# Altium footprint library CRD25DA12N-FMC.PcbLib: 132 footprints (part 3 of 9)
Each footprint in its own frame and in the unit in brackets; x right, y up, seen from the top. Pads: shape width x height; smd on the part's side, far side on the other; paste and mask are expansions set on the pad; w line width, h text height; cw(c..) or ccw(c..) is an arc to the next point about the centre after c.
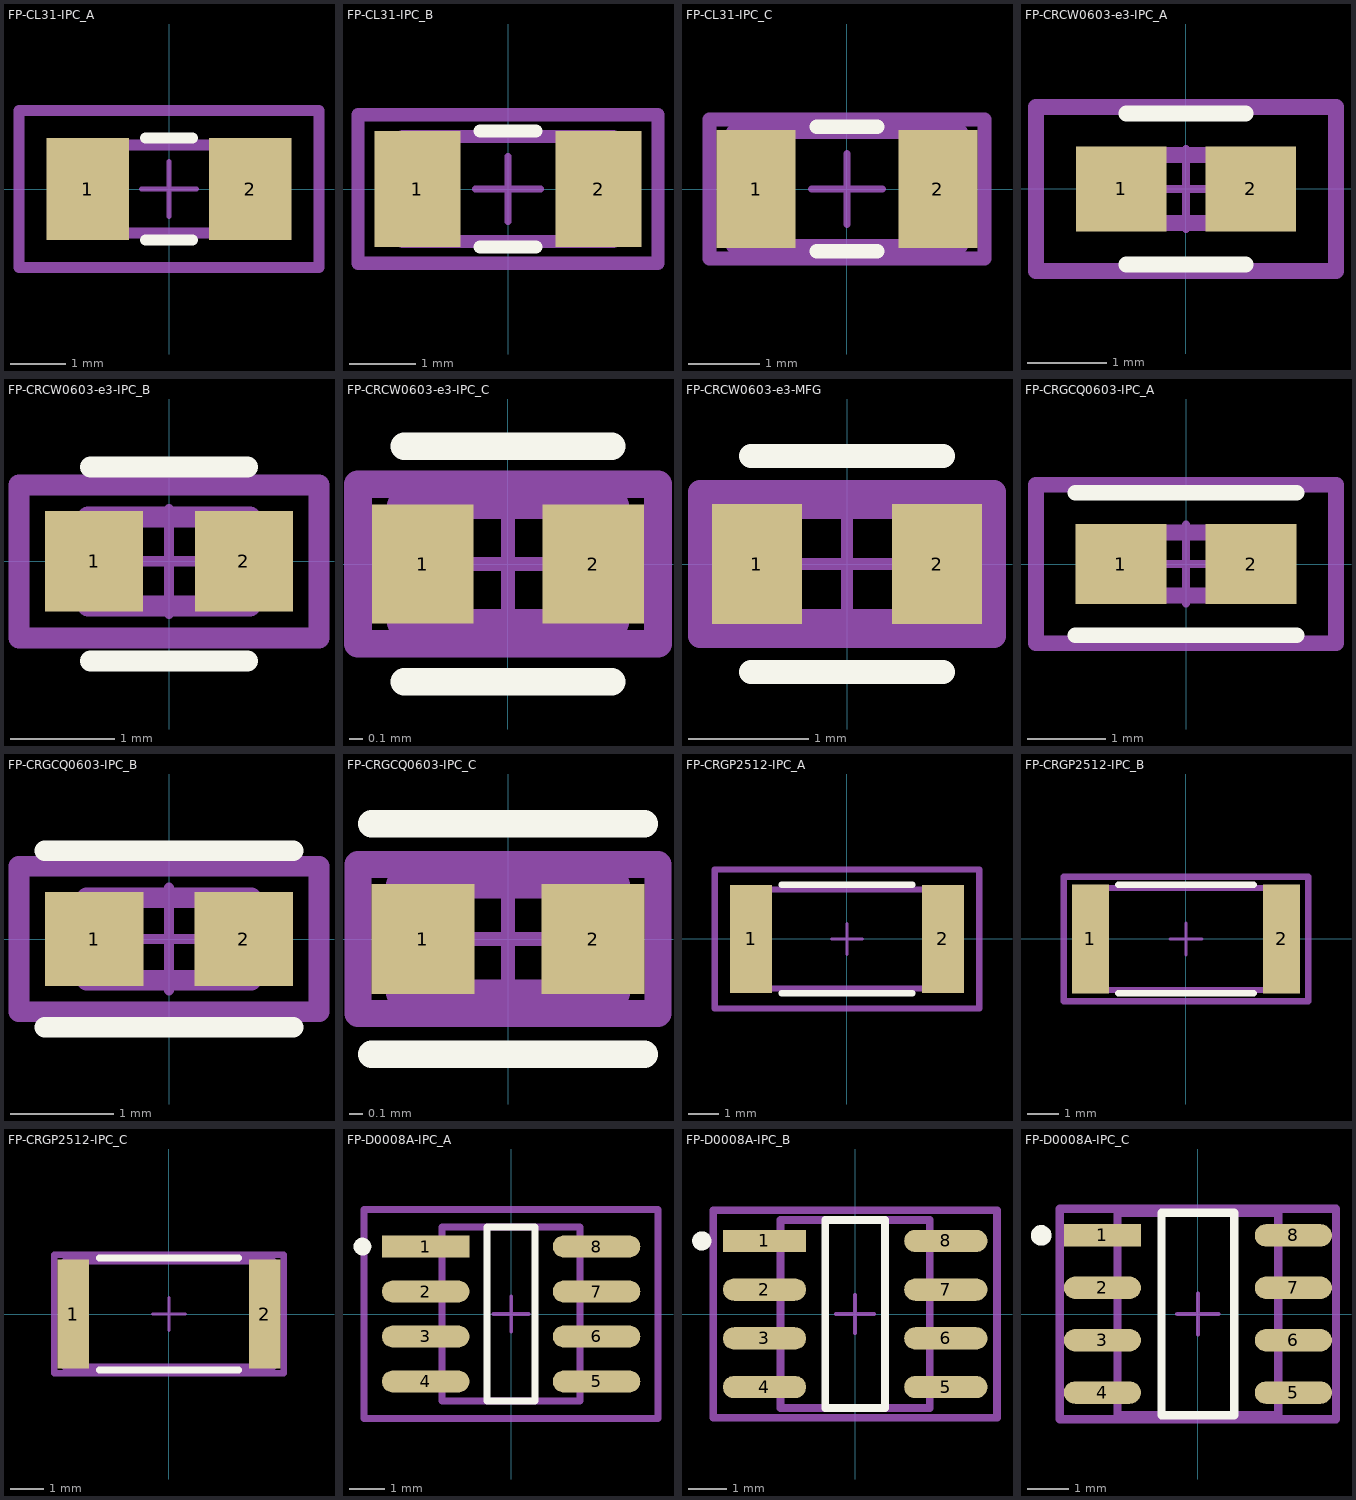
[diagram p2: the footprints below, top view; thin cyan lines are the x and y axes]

## FP-CL31-IPC_A [mm]
pads (2):
  rect 1.505x1.858 smd paste+0 mask+0: 1(-1.476,0) 2(1.476,0)
Top Overlay:
  lines w0.2: -0.424,-0.929 0.424,-0.929 ; -0.424,0.929 0.424,0.929
Mechanical 5:
  lines w0.2: -2.729,-1.429 -2.729,1.429 2.729,1.429 2.729,-1.429 -2.729,-1.429
  text ".Designator" at 0,0.188 h1
Mechanical 13:
  lines w0.2: -1.6,-0.8 -1.6,0.8 1.6,0.8 1.6,-0.8 -1.6,-0.8
Mechanical 15:
  lines w0.2: -2.729,-1.429 -2.729,1.429 2.729,1.429 2.729,-1.429 -2.729,-1.429
Mechanical 16:
  lines w0.1: -0.5,0 0.5,0 ; 0,-0.5 0,0.5
3D body "Cap_Samsung_CL31B105KOFNNNE_eec.STEP": height 0.25, standoff 0, extent -2.729,-1.429 2.729,1.429

## FP-CL31-IPC_B [mm]
pads (2):
  rect 1.305x1.758 smd paste+0 mask+0: 1(-1.376,0) 2(1.376,0)
Top Overlay:
  lines w0.2: -0.424,-0.879 0.424,-0.879 ; -0.424,0.879 0.424,0.879
Mechanical 5:
  lines w0.2: -2.279,-1.129 -2.279,1.129 2.279,1.129 2.279,-1.129 -2.279,-1.129
  text ".Designator" at 0,0.188 h1
Mechanical 13:
  lines w0.2: -1.6,-0.8 -1.6,0.8 1.6,0.8 1.6,-0.8 -1.6,-0.8
Mechanical 15:
  lines w0.2: -2.279,-1.129 -2.279,1.129 2.279,1.129 2.279,-1.129 -2.279,-1.129
Mechanical 16:
  lines w0.1: -0.5,0 0.5,0 ; 0,-0.5 0,0.5
3D body "Cap_Samsung_CL31B105KOFNNNE_eec.STEP": height 0.25, standoff 0, extent -2.279,-1.129 2.279,1.129

## FP-CL31-IPC_C [mm]
pads (2):
  rect 1.105x1.658 smd paste+0 mask+0: 1(-1.276,0) 2(1.276,0)
Top Overlay:
  lines w0.2: -0.424,-0.875 0.424,-0.875 ; -0.424,0.875 0.424,0.875
Mechanical 5:
  lines w0.2: -1.929,-0.975 -1.929,0.975 1.929,0.975 1.929,-0.975 -1.929,-0.975
  text ".Designator" at 0,0.188 h1
Mechanical 13:
  lines w0.2: -1.6,-0.8 -1.6,0.8 1.6,0.8 1.6,-0.8 -1.6,-0.8
Mechanical 15:
  lines w0.2: -1.929,-0.975 -1.929,0.975 1.929,0.975 1.929,-0.975 -1.929,-0.975
Mechanical 16:
  lines w0.1: -0.5,0 0.5,0 ; 0,-0.5 0,0.5
3D body "Cap_Samsung_CL31B105KOFNNNE_eec.STEP": height 0.25, standoff 0, extent -1.929,-0.975 1.929,0.975

## FP-CRCW0603-e3-IPC_A [mm]
pads (2):
  rect 1.135x1.062 smd paste+0 mask+0: 1(-0.815,0) 2(0.815,0)
Top Overlay:
  lines w0.2: -0.75,-0.95 0.75,-0.95 ; -0.75,0.95 0.75,0.95
Mechanical 5:
  lines w0.2: -1.883,-1.031 1.883,-1.031 1.883,1.031 -1.883,1.031 -1.883,-1.031
  text ".Designator" at 0,0.188 h1
Mechanical 13:
  lines w0.2: -0.775,-0.425 0.775,-0.425 0.775,0.425 -0.775,0.425 -0.775,-0.425
Mechanical 15:
  lines w0.2: -1.883,-1.031 1.883,-1.031 1.883,1.031 -1.883,1.031 -1.883,-1.031
Mechanical 16:
  lines w0.1: -0.5,0 0.5,0 ; 0,-0.5 0,0.5
3D body "Res_Vishay_CRCW06033M90FKEC_eec.STEP": height 0.25, standoff 0, extent -1.883,-1.031 1.883,1.031

## FP-CRCW0603-e3-IPC_B [mm]
pads (2):
  rect 0.935x0.962 smd paste+0 mask+0: 1(-0.715,0) 2(0.715,0)
Top Overlay:
  lines w0.2: -0.75,-0.95 0.75,-0.95 ; -0.75,0.9 0.75,0.9
Mechanical 5:
  lines w0.2: -1.433,-0.731 -1.433,0.731 1.433,0.731 1.433,-0.731 -1.433,-0.731
  text ".Designator" at 0,0.188 h1
Mechanical 13:
  lines w0.2: -0.775,-0.425 -0.775,0.425 0.775,0.425 0.775,-0.425 -0.775,-0.425
Mechanical 15:
  lines w0.2: -1.433,-0.731 -1.433,0.731 1.433,0.731 1.433,-0.731 -1.433,-0.731
Mechanical 16:
  lines w0.1: -0.5,0 0.5,0 ; 0,-0.5 0,0.5
3D body "Res_Vishay_CRCW06033M90FKEC_eec.STEP": height 0.25, standoff 0, extent -1.433,-0.731 1.433,0.731

## FP-CRCW0603-e3-IPC_C [mm]
pads (2):
  rect 0.735x0.862 smd paste+0 mask+0: 1(-0.615,0) 2(0.615,0)
Top Overlay:
  lines w0.2: -0.75,-0.85 0.75,-0.85 ; -0.75,0.85 0.75,0.85
Mechanical 5:
  lines w0.2: -1.083,-0.575 1.083,-0.575 1.083,0.575 -1.083,0.575 -1.083,-0.575
  text ".Designator" at 0,0.188 h1
Mechanical 13:
  lines w0.2: -0.775,-0.425 0.775,-0.425 0.775,0.425 -0.775,0.425 -0.775,-0.425
Mechanical 15:
  lines w0.2: -1.083,-0.575 1.083,-0.575 1.083,0.575 -1.083,0.575 -1.083,-0.575
Mechanical 16:
  lines w0.1: -0.5,0 0.5,0 ; 0,-0.5 0,0.5
3D body "Res_Vishay_CRCW06033M90FKEC_eec.STEP": height 0.25, standoff 0, extent -1.083,-0.575 1.083,0.575

## FP-CRCW0603-e3-MFG [mm]
pads (2):
  rect 0.75x1 smd paste+0 mask+0: 1(-0.75,0) 2(0.75,0)
Top Overlay:
  lines w0.2: -0.8,-0.9 0.8,-0.9 ; -0.8,0.9 0.8,0.9
Mechanical 5:
  lines w0.2: -1.225,-0.6 1.225,-0.6 1.225,0.6 -1.225,0.6 -1.225,-0.6
  text ".Designator" at 0,0.188 h1
Mechanical 13:
  lines w0.2: -0.825,-0.475 0.825,-0.475 0.825,0.475 -0.825,0.475 -0.825,-0.475
Mechanical 15:
  lines w0.2: -1.225,-0.6 1.225,-0.6 1.225,0.6 -1.225,0.6 -1.225,-0.6
Mechanical 16:
  lines w0.1: -0.5,0 0.5,0 ; 0,-0.5 0,0.5
3D body "Res_Vishay_CRCW06033M90FKEC_eec.STEP": height 0.25, standoff 0, extent -1.225,-0.6 1.225,0.6

## FP-CRGCQ0603-IPC_A [mm]
pads (2):
  rect 1.158x1.012 smd paste+0 mask+0: 1(-0.827,0) 2(0.827,0)
Top Overlay:
  lines w0.2: -1.406,-0.906 1.406,-0.906 ; -1.406,0.906 1.406,0.906
Mechanical 5:
  lines w0.2: -1.906,-1.006 -1.906,1.006 1.906,1.006 1.906,-1.006 -1.906,-1.006
  text ".Designator" at 0,0.188 h1
Mechanical 13:
  lines w0.2: -0.8,-0.4 -0.8,0.4 0.8,0.4 0.8,-0.4 -0.8,-0.4
Mechanical 15:
  lines w0.2: -1.906,-1.006 -1.906,1.006 1.906,1.006 1.906,-1.006 -1.906,-1.006
Mechanical 16:
  lines w0.1: -0.5,0 0.5,0 ; 0,-0.5 0,0.5
3D body "Res_TE_Connectivity_CRGCQ0603F12R_eec.STEP": height 0.25, standoff 0, extent -1.906,-1.006 1.906,1.006

## FP-CRGCQ0603-IPC_B [mm]
pads (2):
  rect 0.958x0.912 smd paste+0 mask+0: 1(-0.727,0) 2(0.727,0)
Top Overlay:
  lines w0.2: -1.206,-0.856 1.206,-0.856 ; -1.206,0.856 1.206,0.856
Mechanical 5:
  lines w0.2: -1.456,-0.706 -1.456,0.706 1.456,0.706 1.456,-0.706 -1.456,-0.706
  text ".Designator" at 0,0.188 h1
Mechanical 13:
  lines w0.2: -0.8,-0.4 -0.8,0.4 0.8,0.4 0.8,-0.4 -0.8,-0.4
Mechanical 15:
  lines w0.2: -1.456,-0.706 -1.456,0.706 1.456,0.706 1.456,-0.706 -1.456,-0.706
Mechanical 16:
  lines w0.1: -0.5,0 0.5,0 ; 0,-0.5 0,0.5
3D body "Res_TE_Connectivity_CRGCQ0603F12R_eec.STEP": height 0.25, standoff 0, extent -1.456,-0.706 1.456,0.706

## FP-CRGCQ0603-IPC_C [mm]
pads (2):
  rect 0.758x0.812 smd paste+0 mask+0: 1(-0.627,0) 2(0.627,0)
Top Overlay:
  lines w0.2: -1.006,-0.85 1.006,-0.85 ; -1.006,0.85 1.006,0.85
Mechanical 5:
  lines w0.2: -1.106,-0.55 -1.106,0.55 1.106,0.55 1.106,-0.55 -1.106,-0.55
  text ".Designator" at 0,0.188 h1
Mechanical 13:
  lines w0.2: -0.8,-0.4 -0.8,0.4 0.8,0.4 0.8,-0.4 -0.8,-0.4
Mechanical 15:
  lines w0.2: -1.106,-0.55 -1.106,0.55 1.106,0.55 1.106,-0.55 -1.106,-0.55
Mechanical 16:
  lines w0.1: -0.5,0 0.5,0 ; 0,-0.5 0,0.5
3D body "Res_TE_Connectivity_CRGCQ0603F12R_eec.STEP": height 0.25, standoff 0, extent -1.106,-0.55 1.106,0.55

## FP-CRGP2512-IPC_A [mm]
pads (2):
  rect 1.358x3.506 smd paste+0 mask+0: 1(-3.102,0) 2(3.102,0)
Top Overlay:
  lines w0.2: -2.123,-1.753 2.123,-1.753 ; -2.123,1.753 2.123,1.753
Mechanical 5:
  lines w0.2: -4.281,-2.253 -4.281,2.253 4.281,2.253 4.281,-2.253 -4.281,-2.253
  text ".Designator" at 0,0.188 h1
Mechanical 13:
  lines w0.2: -3.175,-1.6 -3.175,1.6 3.175,1.6 3.175,-1.6 -3.175,-1.6
Mechanical 15:
  lines w0.2: -4.281,-2.253 -4.281,2.253 4.281,2.253 4.281,-2.253 -4.281,-2.253
Mechanical 16:
  lines w0.1: -0.5,0 0.5,0 ; 0,-0.5 0,0.5
3D body "Res_TE_CRGP2512F47R_eec.STEP": height 0.25, standoff 0, extent -4.281,-2.253 4.281,2.253

## FP-CRGP2512-IPC_B [mm]
pads (2):
  rect 1.158x3.406 smd paste+0 mask+0: 1(-3.002,0) 2(3.002,0)
Top Overlay:
  lines w0.2: -2.123,-1.703 2.123,-1.703 ; -2.123,1.703 2.123,1.703
Mechanical 5:
  lines w0.2: -3.831,-1.953 3.831,-1.953 3.831,1.953 -3.831,1.953 -3.831,-1.953
  text ".Designator" at 0,0.188 h1
Mechanical 13:
  lines w0.2: -3.175,-1.6 3.175,-1.6 3.175,1.6 -3.175,1.6 -3.175,-1.6
Mechanical 15:
  lines w0.2: -3.831,-1.953 3.831,-1.953 3.831,1.953 -3.831,1.953 -3.831,-1.953
Mechanical 16:
  lines w0.1: -0.5,0 0.5,0 ; 0,-0.5 0,0.5
3D body "Res_TE_CRGP2512F47R_eec.STEP": height 0.25, standoff 0, extent -3.831,-1.953 3.831,1.953

## FP-CRGP2512-IPC_C [mm]
pads (2):
  rect 0.958x3.306 smd paste+0 mask+0: 1(-2.902,0) 2(2.902,0)
Top Overlay:
  lines w0.2: -2.123,-1.7 2.123,-1.7 ; -2.123,1.7 2.123,1.7
Mechanical 5:
  lines w0.2: -3.481,-1.8 -3.481,1.8 3.481,1.8 3.481,-1.8 -3.481,-1.8
  text ".Designator" at 0,0.188 h1
Mechanical 13:
  lines w0.2: -3.175,-1.6 -3.175,1.6 3.175,1.6 3.175,-1.6 -3.175,-1.6
Mechanical 15:
  lines w0.2: -3.481,-1.8 -3.481,1.8 3.481,1.8 3.481,-1.8 -3.481,-1.8
Mechanical 16:
  lines w0.1: -0.5,0 0.5,0 ; 0,-0.5 0,0.5
3D body "Res_TE_CRGP2512F47R_eec.STEP": height 0.25, standoff 0, extent -3.481,-1.8 3.481,1.8

## FP-D0008A-IPC_A [mm]
pads (8):
  rect 2.469x0.622 smd paste+0 mask+0: 1(-2.414,1.905)
  rrect100% 2.469x0.622 smd paste+0 mask+0: 2(-2.414,0.635) 3(-2.414,-0.635) 4(-2.414,-1.905) 5(2.414,-1.905) 6(2.414,-0.635) 7(2.414,0.635) 8(2.414,1.905)
Top Overlay:
  circle w0.25: c-4.198,1.905 r0.125
  lines w0.2: -0.679,-2.452 0.679,-2.452 0.679,2.452 -0.679,2.452 -0.679,-2.452
Mechanical 5:
  lines w0.2: -4.148,-2.953 4.148,-2.953 4.148,2.953 -4.148,2.953 -4.148,-2.953
  text ".Designator" at 0,0.188 h1
Mechanical 13:
  lines w0.2: -1.947,-2.452 1.947,-2.452 1.947,2.452 -1.947,2.452 -1.947,-2.452
Mechanical 15:
  lines w0.2: -4.148,-2.953 4.148,-2.953 4.148,2.953 -4.148,2.953 -4.148,-2.953
Mechanical 16:
  lines w0.1: -0.5,0 0.5,0 ; 0,-0.5 0,0.5
3D body "IC_Texas_Instruments_ISO7220ADR_eec.STEP": height 0.25, standoff 0, extent -4.148,-2.953 4.148,2.953

## FP-D0008A-IPC_B [mm]
pads (8):
  rect 2.169x0.582 smd paste+0 mask+0: 1(-2.364,1.905)
  rrect100% 2.169x0.582 smd paste+0 mask+0: 2(-2.364,0.635) 3(-2.364,-0.635) 4(-2.364,-1.905) 5(2.364,-1.905) 6(2.364,-0.635) 7(2.364,0.635) 8(2.364,1.905)
Top Overlay:
  circle w0.25: c-3.998,1.905 r0.125
  lines w0.2: -0.779,-2.452 -0.779,2.452 0.779,2.452 0.779,-2.452 -0.779,-2.452
Mechanical 5:
  lines w0.2: -3.698,-2.702 -3.698,2.702 3.698,2.702 3.698,-2.702 -3.698,-2.702
  text ".Designator" at 0,0.188 h1
Mechanical 13:
  lines w0.2: -1.947,-2.452 -1.947,2.452 1.947,2.452 1.947,-2.452 -1.947,-2.452
Mechanical 15:
  lines w0.2: -3.698,-2.702 -3.698,2.702 3.698,2.702 3.698,-2.702 -3.698,-2.702
Mechanical 16:
  lines w0.1: -0.5,0 0.5,0 ; 0,-0.5 0,0.5
3D body "IC_Texas_Instruments_ISO7220ADR_eec.STEP": height 0.25, standoff 0, extent -3.698,-2.702 3.698,2.702

## FP-D0008A-IPC_C [mm]
pads (8):
  rect 1.869x0.542 smd paste+0 mask+0: 1(-2.314,1.905)
  rrect100% 1.869x0.542 smd paste+0 mask+0: 2(-2.314,0.635) 3(-2.314,-0.635) 4(-2.314,-1.905) 5(2.314,-1.905) 6(2.314,-0.635) 7(2.314,0.635) 8(2.314,1.905)
Top Overlay:
  circle w0.25: c-3.798,1.905 r0.125
  lines w0.2: -0.879,-2.452 -0.879,2.452 0.879,2.452 0.879,-2.452 -0.879,-2.452
Mechanical 5:
  lines w0.2: -3.348,-2.552 -3.348,2.552 3.348,2.552 3.348,-2.552 -3.348,-2.552
  text ".Designator" at 0,0.188 h1
Mechanical 13:
  lines w0.2: -1.947,-2.452 -1.947,2.452 1.947,2.452 1.947,-2.452 -1.947,-2.452
Mechanical 15:
  lines w0.2: -3.348,-2.552 -3.348,2.552 3.348,2.552 3.348,-2.552 -3.348,-2.552
Mechanical 16:
  lines w0.1: -0.5,0 0.5,0 ; 0,-0.5 0,0.5
3D body "IC_Texas_Instruments_ISO7220ADR_eec.STEP": height 0.25, standoff 0, extent -3.348,-2.552 3.348,2.552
